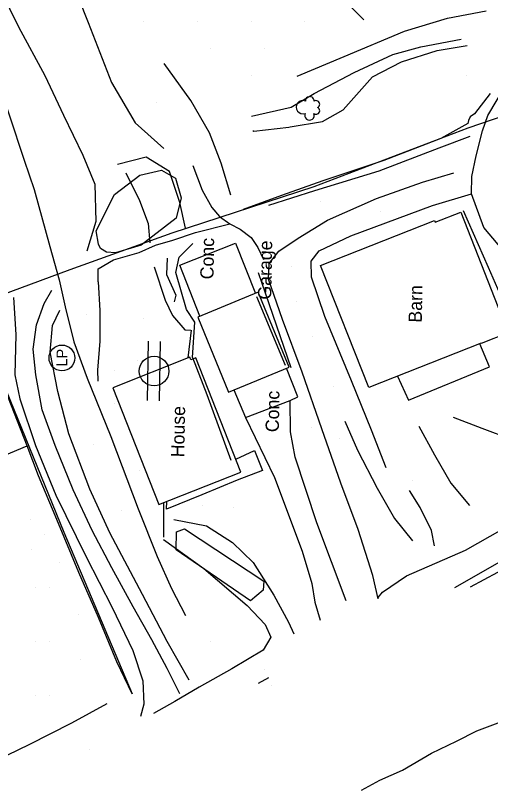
# Model space of a CAD drawing. Extents: x 19528164 to 19545171, y 7585743 to 7602745.
# Drawn here: x 19532117.5 to 19532293.9, y 7588342 to 7588627.3 of the extents above; entities that cross this region are included whole.
import ezdxf

# ---------------------------------------------------------------- set-up
doc = ezdxf.new("R2010")
doc.units = 0
for name, color, linetype in [('Default', 7, 'Continuous'), ('PhoBreakLine', 7, 'Continuous'), ('PhoBuilding', 7, 'Continuous'), ('PhoConcreteSlab', 7, 'Continuous'), ('PhoDrainageArrow', 7, 'Continuous'), ('PhoEdgeEntrancePaved', 7, 'Continuous'), ('PhoEdgeSidewalk', 7, 'Continuous'), ('PhoFence', 7, 'Continuous'), ('PhoISAEPoints', 7, 'Continuous'), ('PhoNotesDesign', 7, 'Continuous'), ('PhoRetainingWall', 7, 'Continuous'), ('PhoVegetation', 7, 'Continuous'), ('SurNaturalCells', 7, 'Continuous'), ('SurROWRail', 7, 'Continuous')]:
    doc.layers.add(name, color=color, linetype=linetype)

# ---------------------------------------------------------------- blocks, each defined once
blk = doc.blocks.new('PP')
at = {"layer": 'Default'}
for p, q in [((-11, 2.2), (11, 2.2)), ((-11, -2.2), (11, -2.2))]:
    blk.add_line(p, q, dxfattribs=at)
blk.add_circle((0, 0), 5.51, dxfattribs=at)
blk = doc.blocks.new('TRDC')
at = {"layer": 'PhoVegetation'}
for centre, radius, start, end in [((0.07, 3.96), 4.92, 338.2051, 201.7949), ((-5.96, -1.07), 3.52, 65.4824, 294.5175), ((4.86, -1.07), 3.21, 265.9982, 94.0018), ((-2.37, -5.89), 2.68, 142.7501, 335.3223), ((2.46, -5.82), 2.67, 206.5242, 35.4033)]:
    blk.add_arc(centre, radius, start, end, dxfattribs=at)

msp = doc.modelspace()

# ---------------------------------------------------------------- linework, layer by layer
at = {"layer": 'PhoBreakLine'}
for p, q in [((19532217.83, 7588497.48), (19532207.15, 7588522.94)), ((19532211.43, 7588381.68), (19532207.63, 7588379.59))]:
    msp.add_line(p, q, dxfattribs=at)
for points in [[(19532117.51, 7588692.95), (19532122.03, 7588680.55), (19532133.22, 7588653.08), (19532144.58, 7588624.72), (19532153.24, 7588602.44), (19532161.91, 7588587.52), (19532172.57, 7588577.92)], [(19532096.38, 7588686.82), (19532099.71, 7588672.12), (19532104.43, 7588654.87), (19532112.03, 7588636.79), (19532118.7, 7588623.11), (19532128.48, 7588605), (19532135.37, 7588590.32), (19532142.54, 7588575.49), (19532146.96, 7588564.79), (19532147.32, 7588550.88), (19532144.08, 7588539.85)], [(19532222.13, 7588604.78), (19532239.59, 7588612.1), (19532261.91, 7588621.42), (19532277.9, 7588626.34), (19532292.31, 7588629.01)], [(19532205.17, 7588589.97), (19532219.9, 7588593.28), (19532228.36, 7588598.34), (19532243.21, 7588606.13), (19532257.6, 7588612.83), (19532267.95, 7588615.7), (19532282.94, 7588618.54)], [(19532205.59, 7588584.67), (19532206.03, 7588584.35), (19532219.07, 7588585.89), (19532219.54, 7588585.94), (19532231.46, 7588587.94), (19532239.22, 7588592.3), (19532250.02, 7588604.51), (19532260.83, 7588610.12), (19532274.01, 7588614.28), (19532285.2, 7588616.11)], [(19532345.9, 7588470.96), (19532343.31, 7588478.04), (19532339.87, 7588480.04), (19532335.79, 7588483.95), (19532326.74, 7588499.82), (19532318.11, 7588515.82), (19532304.07, 7588533.72), (19532291.41, 7588548.65), (19532286.82, 7588561.13), (19532286.99, 7588567.53), (19532288.58, 7588575.28), (19532290.91, 7588584.54), (19532292.84, 7588590.21), (19532299.79, 7588601.82), (19532308.68, 7588611.08)], [(19532197.42, 7588560.69), (19532193.94, 7588572.5), (19532189.54, 7588583.76), (19532182.67, 7588595.81), (19532172.73, 7588609.43)], [(19532109.52, 7588607.03), (19532115.19, 7588590.42), (19532120.72, 7588573.63), (19532124.47, 7588562.7), (19532130.34, 7588541.61), (19532133.79, 7588529.22), (19532135.99, 7588519.25), (19532139.17, 7588506.2), (19532144.14, 7588492.76), (19532152.92, 7588471.17), (19532163.12, 7588444.26), (19532170.13, 7588426.63), (19532175.48, 7588414.82), (19532180.69, 7588404.74)], [(19532293.76, 7588598.35), (19532287.89, 7588590.87), (19532286.26, 7588589.67), (19532285.67, 7588588.33), (19532285.5, 7588587.18), (19532275.44, 7588581.67), (19532254.29, 7588573.46), (19532231.64, 7588565.91), (19532216.26, 7588560.55), (19532202.03, 7588555.38)], [(19532211.57, 7588556.9), (19532228.72, 7588562.39), (19532252.5, 7588569.63), (19532274.86, 7588578.17), (19532286.37, 7588582.5)], [(19532180.67, 7588548.42), (19532178.59, 7588557.92), (19532174.74, 7588569.39), (19532166.06, 7588574.79), (19532155.42, 7588571.99)], [(19532183.37, 7588571.67), (19532186.87, 7588562.55), (19532190.41, 7588556.03), (19532193.24, 7588552.69), (19532197.08, 7588550.02), (19532200.93, 7588548.1), (19532205.03, 7588544.96), (19532207.51, 7588541.23), (19532209.65, 7588536.73)], [(19532158.5, 7588568.99), (19532163.56, 7588558.73), (19532166.79, 7588550.14), (19532167.36, 7588542.98)], [(19532252.22, 7588410.88), (19532250.19, 7588419.55), (19532244.74, 7588436.7), (19532238.26, 7588453.85), (19532231.24, 7588473.97), (19532223.97, 7588494.99), (19532216.6, 7588514.53), (19532211.46, 7588529.55), (19532211.71, 7588535.36), (19532215.24, 7588539.82), (19532222.45, 7588544.72), (19532233.39, 7588551.41), (19532251.52, 7588559.36), (19532268.57, 7588565.42), (19532280.31, 7588568.89)], [(19532255.16, 7588459.49), (19532249.66, 7588473.48), (19532242.32, 7588491.83), (19532232.4, 7588515.7), (19532227.43, 7588530.23), (19532227.24, 7588536.22), (19532230.29, 7588540), (19532242.05, 7588545.52), (19532272.3, 7588556.81), (19532286.82, 7588561.13)], [(19532283.78, 7588554.91), (19532293.02, 7588533.95), (19532303.37, 7588510.21)], [(19532148.2, 7588528.56), (19532148.29, 7588533.27), (19532153.91, 7588536.67), (19532163.5, 7588539.43), (19532169.57, 7588542.06), (19532175.97, 7588543.94), (19532184.39, 7588546.76), (19532197.08, 7588550.02)], [(19532183.24, 7588500.49), (19532184.06, 7588513.57), (19532181.07, 7588518.3), (19532177.04, 7588531.98), (19532178.34, 7588537.66), (19532183.34, 7588542.69)], [(19532173.86, 7588537.33), (19532173.61, 7588531.25), (19532177.02, 7588523.6), (19532176.42, 7588521.08)], [(19532168.97, 7588534.11), (19532173.07, 7588521.73), (19532175.85, 7588516.02), (19532180.46, 7588510.74), (19532182.58, 7588510.58)], [(19532219.86, 7588496.64), (19532210.43, 7588523.98), (19532207.75, 7588531.9)], [(19532148.2, 7588528.56), (19532148.91, 7588517.84), (19532148.91, 7588506.48), (19532147.94, 7588495.78), (19532148.14, 7588491.69)], [(19532178.6, 7588375.72), (19532173.85, 7588385.04), (19532168.2, 7588395.7), (19532161.24, 7588408.01), (19532153.31, 7588422.45), (19532146.01, 7588436.29), (19532138.99, 7588451.32), (19532132.23, 7588467.78), (19532127.49, 7588480.97), (19532125.11, 7588493.98), (19532124.11, 7588503.52), (19532125.39, 7588512.57), (19532128.24, 7588520.44), (19532131.07, 7588525.36)], [(19532116.83, 7588522.64), (19532117.64, 7588509.01), (19532117.28, 7588493.99), (19532119.14, 7588485.06), (19532124.99, 7588467.81), (19532132.55, 7588449.37), (19532143.77, 7588426.52), (19532153.46, 7588407.76), (19532161.09, 7588391.78), (19532164.76, 7588380.5), (19532165.19, 7588371.87), (19532164.01, 7588367.23)], [(19532182, 7588380.82), (19532173.83, 7588395.15), (19532164.71, 7588412.58), (19532152.59, 7588435.47), (19532145.13, 7588451.56), (19532137.29, 7588472.15), (19532133.24, 7588487.79), (19532130.41, 7588502.48), (19532131.31, 7588512.28), (19532133.95, 7588518.04)], [(19532183.24, 7588500.49), (19532188.57, 7588486.77), (19532197.54, 7588462.34)], [(19532078.41, 7588477.17), (19532084.33, 7588462.92), (19532088.18, 7588455.62), (19532094.08, 7588456.75), (19532110.89, 7588463.13), (19532121.83, 7588467.68), (19532112.51, 7588491.68), (19532109.97, 7588490.85), (19532103.52, 7588488.88), (19532095.71, 7588486.59), (19532088.76, 7588484.49), (19532080.39, 7588482.1)], [(19532239.83, 7588476.79), (19532244.5, 7588466.04), (19532251.76, 7588452), (19532258.25, 7588440.76), (19532264.86, 7588432.41)], [(19532323.96, 7588459.12), (19532312.99, 7588464.07), (19532302.03, 7588469.91), (19532290.82, 7588474.16), (19532280.17, 7588478.15)], [(19532267.22, 7588474.93), (19532273.11, 7588464.28), (19532279.16, 7588453.86), (19532286.1, 7588445.54)], [(19532160.91, 7588375.73), (19532155.19, 7588387.61), (19532148.38, 7588403.95), (19532141.09, 7588420.68), (19532132.93, 7588440.31), (19532126.04, 7588456.54), (19532121.83, 7588467.68)], [(19532252.12, 7588411.37), (19532253.79, 7588413.38), (19532262.73, 7588419.5), (19532284.65, 7588428.98), (19532306.63, 7588441.53), (19532321.96, 7588450.77), (19532330.46, 7588454.68), (19532335.45, 7588457.14)], [(19532273.13, 7588430.58), (19532271.94, 7588436.31), (19532267.74, 7588444.79), (19532263.86, 7588451.12)], [(19532347.5, 7588450.83), (19532341.52, 7588449.75), (19532335.2, 7588447.94), (19532325.46, 7588441.76), (19532317.35, 7588436.5), (19532301.55, 7588426.98), (19532280.46, 7588414.98)], [(19532286.5, 7588415.38), (19532311.76, 7588428.95), (19532332.74, 7588440.52), (19532343.37, 7588446.1)], [(19532176.31, 7588440.38), (19532188.44, 7588438.04), (19532198.06, 7588431.85), (19532205.76, 7588424.41), (19532213.39, 7588412.3), (19532218.91, 7588402.29), (19532220.89, 7588398.01)], [(19532172.49, 7588432.95), (19532187.41, 7588422.15), (19532203.55, 7588408.51), (19532210.18, 7588401.41), (19532212.32, 7588396.66), (19532209.45, 7588391.9), (19532197.84, 7588385), (19532185.75, 7588378.23), (19532176.72, 7588372.8), (19532168.77, 7588368.46)], [(19532246.02, 7588339.94), (19532252.76, 7588343.69), (19532261.21, 7588347.33), (19532271.95, 7588353.7), (19532281.21, 7588358.15), (19532288.75, 7588361.93), (19532299.67, 7588366.04), (19532310.98, 7588368.83), (19532323.6, 7588371.25), (19532335.41, 7588373.29), (19532347.14, 7588376.67), (19532358.39, 7588381.89), (19532368.65, 7588385.91), (19532376.29, 7588388.6), (19532373.95, 7588394.78), (19532370.32, 7588397.48), (19532363.01, 7588399.87)], [(19532095.09, 7588342.96), (19532106.67, 7588349.23), (19532122.65, 7588356.91), (19532138.42, 7588364.98), (19532151.55, 7588372.11)]]:
    msp.add_lwpolyline(points, dxfattribs=at)
at = {"layer": 'PhoBuilding'}
for points in [[(19532248.66, 7588489.33), (19532230.81, 7588534.56), (19532273.13, 7588551.26), (19532273.36, 7588550.66), (19532282.82, 7588554.39), (19532300.44, 7588509.62), (19532290.43, 7588505.68), (19532290.4, 7588505.76)], [(19532185.2, 7588515.39), (19532196.67, 7588487.64), (19532219.09, 7588496.9), (19532207.62, 7588524.65)], [(19532153.67, 7588489.2), (19532170.81, 7588445.89), (19532201.23, 7588457.93), (19532184.47, 7588500.31), (19532182.65, 7588499.59), (19532182.28, 7588500.52)]]:
    msp.add_lwpolyline(points, close=True, dxfattribs=at)
at = {"layer": 'PhoConcreteSlab'}
for points in [[(19532186.03, 7588515.73), (19532178.5, 7588534.66), (19532199.21, 7588542.89), (19532206.63, 7588524.24)], [(19532259.29, 7588493.52), (19532263.49, 7588484.65), (19532293.54, 7588497.02), (19532289.9, 7588505.57)]]:
    msp.add_lwpolyline(points, dxfattribs=at)
at = {"layer": 'PhoDrainageArrow'}
msp.add_lwpolyline([(19532195.25, 7588879.95), (19532195.05, 7588858.82), (19532204.3, 7588842.7), (19532211.04, 7588822.04), (19532211.34, 7588766.98), (19532202.46, 7588727.04), (19532202.15, 7588699.23), (19532206.12, 7588682.62), (19532210.44, 7588661.67), (19532246.9, 7588625.62)], dxfattribs=at)
at = {"layer": 'PhoEdgeEntrancePaved'}
msp.add_lwpolyline([(19532198.56, 7588488.42), (19532202.9, 7588478.2), (19532219.54, 7588484.55), (19532222.37, 7588485.88), (19532218.2, 7588496.53)], dxfattribs=at)
at = {"layer": 'PhoEdgeSidewalk'}
msp.add_lwpolyline([(19532199.32, 7588462.75), (19532206.3, 7588465.9), (19532209.22, 7588458.5), (19532199.87, 7588455), (19532186.75, 7588449.46), (19532173.59, 7588444.13), (19532173.72, 7588447.05)], dxfattribs=at)
at = {"layer": 'PhoFence'}
for points in [[(19532413.6, 7588629.09), (19532354.85, 7588609.21), (19532285.42, 7588585.45), (19532228.32, 7588563.7), (19532175.6, 7588546.51), (19532137.73, 7588532.93), (19532101.25, 7588519.42), (19532059.87, 7588505.63)], [(19532101.25, 7588519.42), (19532135.52, 7588435.6), (19532160.91, 7588375.73)]]:
    msp.add_lwpolyline(points, dxfattribs=at)
at = {"layer": 'PhoISAEPoints'}
for p, q in [((19532165, 7588625), (19532165, 7588625)), ((19532185, 7588625), (19532185, 7588625)), ((19532205, 7588625), (19532205, 7588625)), ((19532225, 7588625), (19532225, 7588625)), ((19532190, 7588615), (19532190, 7588615)), ((19532190, 7588615), (19532190, 7588615)), ((19532210, 7588615), (19532210, 7588615)), ((19532205, 7588605), (19532205, 7588605)), ((19532285, 7588605), (19532285, 7588605)), ((19532170, 7588595), (19532170, 7588595)), ((19532170, 7588595), (19532170, 7588595)), ((19532230.9, 7588558.33), (19532230.9, 7588558.33)), ((19532252.93, 7588554.45), (19532252.93, 7588554.45)), ((19532220.06, 7588534.09), (19532220.06, 7588534.09)), ((19532221.7, 7588521.18), (19532221.7, 7588521.18)), ((19532143.79, 7588516.31), (19532143.79, 7588516.31)), ((19532165, 7588515), (19532165, 7588515)), ((19532227.97, 7588508.3), (19532227.97, 7588508.3)), ((19532162.95, 7588499.24), (19532162.95, 7588499.24)), ((19532154.44, 7588495.5), (19532154.44, 7588495.5)), ((19532235.55, 7588489.64), (19532235.55, 7588489.64)), ((19532154.14, 7588483.31), (19532154.14, 7588483.31)), ((19532227.59, 7588474.57), (19532227.59, 7588474.57)), ((19532146.66, 7588468.23), (19532146.66, 7588468.23)), ((19532237.88, 7588470.35), (19532237.88, 7588470.35)), ((19532163.47, 7588458.55), (19532163.47, 7588458.55)), ((19532265, 7588455), (19532265, 7588455)), ((19532186.87, 7588445.45), (19532186.87, 7588445.45)), ((19532156.91, 7588443.66), (19532156.91, 7588443.66)), ((19532198.56, 7588444.84), (19532198.56, 7588444.84)), ((19532123.22, 7588440.5), (19532123.22, 7588440.5)), ((19532128.42, 7588434.81), (19532128.42, 7588434.81)), ((19532123.58, 7588429.28), (19532123.58, 7588429.28)), ((19532133.82, 7588424.24), (19532133.82, 7588424.24)), ((19532125, 7588415), (19532125, 7588415)), ((19532130, 7588415), (19532130, 7588415)), ((19532130, 7588415), (19532130, 7588415)), ((19532141.08, 7588405.22), (19532141.08, 7588405.22)), ((19532125, 7588395), (19532125, 7588395)), ((19532130, 7588395), (19532130, 7588395)), ((19532130, 7588395), (19532130, 7588395)), ((19532190, 7588395), (19532190, 7588395)), ((19532141.67, 7588388.55), (19532141.67, 7588388.55)), ((19532209.85, 7588384.85), (19532209.85, 7588384.85)), ((19532212.66, 7588378.66), (19532212.66, 7588378.66)), ((19532125, 7588375), (19532125, 7588375)), ((19532130, 7588375), (19532130, 7588375)), ((19532130, 7588375), (19532130, 7588375)), ((19532145, 7588355), (19532145, 7588355))]:
    msp.add_line(p, q, dxfattribs=at)
at = {"layer": 'PhoRetainingWall'}
for p, q in [((19532181.7, 7588500.29), (19532182.89, 7588510.62)), ((19532172.63, 7588433.77), (19532172.62, 7588446.61))]:
    msp.add_line(p, q, dxfattribs=at)
at = {"layer": 'PhoVegetation'}
for points in [[(19532147.44, 7588547.4), (19532154.24, 7588560.86), (19532163.73, 7588568.02), (19532171.76, 7588569.97), (19532176.97, 7588566.98), (19532179.09, 7588559.6), (19532177.25, 7588552.17), (19532164.17, 7588542.07), (19532154.65, 7588539.31), (19532151.35, 7588539.5), (19532149.15, 7588540.88), (19532148.37, 7588542.53)], [(19532204.73, 7588410.22), (19532177.21, 7588429.1), (19532177.3, 7588435.73), (19532180.24, 7588436.94), (19532209.69, 7588417.51), (19532209.44, 7588414.14)]]:
    msp.add_lwpolyline(points, close=True, dxfattribs=at)
at = {"layer": 'SurNaturalCells'}
msp.add_circle((19532134.79, 7588500.27), 4.8, dxfattribs=at)
at = {"layer": 'SurROWRail'}
for points in [[(19532240.32, 7588410.19), (19532229.35, 7588439.1), (19532221.41, 7588463.53), (19532219.58, 7588472.81), (19532219.54, 7588484.55)], [(19532202.9, 7588478.2), (19532213.74, 7588455.96), (19532223.99, 7588428.55), (19532227.6, 7588416.56), (19532228.67, 7588409.71), (19532230.63, 7588402.99)]]:
    msp.add_lwpolyline(points, dxfattribs=at)

# ---------------------------------------------------------------- block references
at = {"layer": 'PhoVegetation', "xscale": 0.499999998, "yscale": 0.49999999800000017, "rotation": 89.00825751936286}
msp.add_blockref('TRDC', (19532226.2, 7588593.2), dxfattribs=at)
at = {"layer": 'SurNaturalCells', "xscale": 0.999999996, "yscale": 0.9999999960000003, "rotation": 89.00825751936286}
msp.add_blockref('PP', (19532168.97, 7588495.41), dxfattribs=at)

# ---------------------------------------------------------------- texts
at = {"layer": 'PhoNotesDesign'}
for s, rotation, p in [('Conc', 89.0465, (19532191.04, 7588529.39)), ('Garage', 89.0083, (19532212.46, 7588521.88)), ('Barn', 89.0083, (19532268.36, 7588513.34)), ('Conc', 89.0465, (19532215.28, 7588472.71)), ('House', 89.0083, (19532180.2, 7588463.4))]:
    msp.add_text(s, height=4.92, rotation=rotation, dxfattribs=at).set_placement(p)
at = {"layer": 'SurNaturalCells'}
msp.add_text('LP', height=3.999, rotation=89.5038, dxfattribs=at).set_placement((19532136.76, 7588497.08))

doc.saveas('drawing.dxf')
